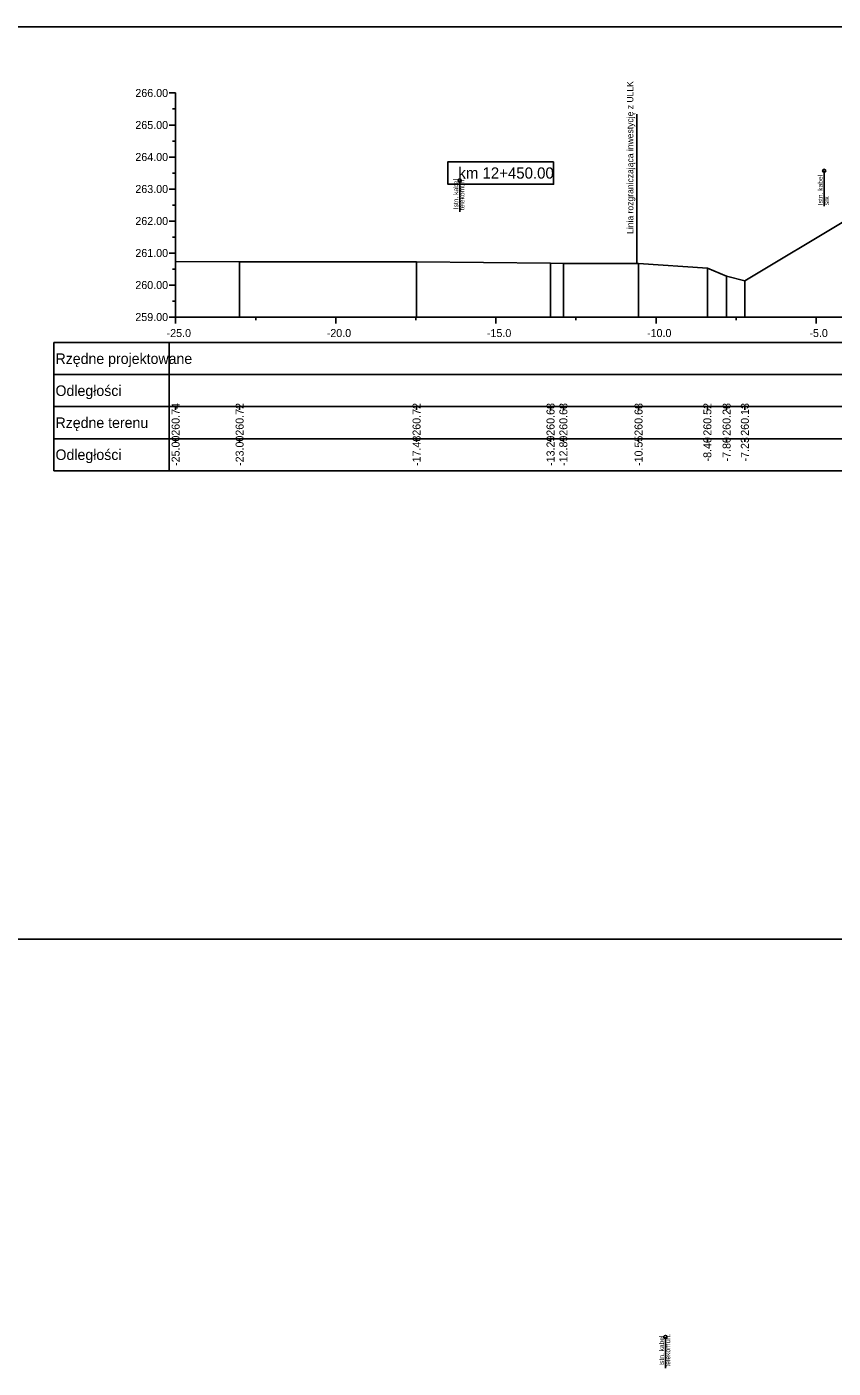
# Model space of a CAD drawing. Extents: x 6516023 to 6560129, y 5513077 to 5529206.
# Drawn here: x 6516864.76 to 6516889.94, y 5513349.38 to 5513391.29 of the extents above; entities that cross this region are included whole.
import ezdxf

# ---------------------------------------------------------------- set-up
doc = ezdxf.new("R2010")
doc.units = 0
for name, color, linetype in [('TOR_PRZEK_P-kable', 7, 'Continuous'), ('TOR_PRZEK_P-tabelka istniejace', 7, 'Continuous'), ('TOR_PRZEK_P-tabelka projektowane', 7, 'Continuous'), ('TOR_PRZEK_P-teren istniejacy', 7, 'Continuous'), ('TOR_PRZEK_P-uklad odniesienia', 7, 'Continuous'), ('TOR_PS_T-granica PKP-projektowana', 7, 'Continuous'), ('TOR_RAMKI-ramka+tabelka 1', 7, 'Continuous')]:
    doc.layers.add(name, color=color, linetype=linetype)

msp = doc.modelspace()

# ---------------------------------------------------------------- linework, layer by layer
at = {"layer": 'TOR_PRZEK_P-kable'}
for p, q in [((6516889.66, 5513386.791), (6516889.66, 5513385.682)), ((6516878.279, 5513386.488), (6516878.279, 5513385.514)), ((6516884.704, 5513350.355), (6516884.704, 5513349.382))]:
    msp.add_line(p, q, dxfattribs=at)
for centre in [(6516878.279, 5513386.488), (6516889.66, 5513386.791), (6516884.704, 5513350.355)]:
    msp.add_circle(centre, 0.05, dxfattribs=at)
at = {"layer": 'TOR_PRZEK_P-tabelka istniejace'}
for p, q in [((6516865.61, 5513379.422), (6516865.61, 5513377.422)), ((6516869.21, 5513379.422), (6516869.21, 5513377.422)), ((6516869.41, 5513379.322), (6516869.41, 5513379.422)), ((6516871.408, 5513379.322), (6516871.408, 5513379.422)), ((6516876.933, 5513379.322), (6516876.933, 5513379.422)), ((6516881.116, 5513379.322), (6516881.116, 5513379.422)), ((6516881.517, 5513379.322), (6516881.517, 5513379.422)), ((6516883.864, 5513379.322), (6516883.864, 5513379.422)), ((6516886.013, 5513379.322), (6516886.013, 5513379.422)), ((6516886.613, 5513379.322), (6516886.613, 5513379.422)), ((6516887.184, 5513379.322), (6516887.184, 5513379.422)), ((6516865.61, 5513378.422), (6516919.41, 5513378.422)), ((6516869.41, 5513378.322), (6516869.41, 5513378.422)), ((6516871.408, 5513378.322), (6516871.408, 5513378.422)), ((6516876.933, 5513378.322), (6516876.933, 5513378.422)), ((6516881.116, 5513378.322), (6516881.116, 5513378.422)), ((6516881.517, 5513378.322), (6516881.517, 5513378.422)), ((6516883.864, 5513378.322), (6516883.864, 5513378.422)), ((6516886.013, 5513378.322), (6516886.013, 5513378.422)), ((6516886.613, 5513378.322), (6516886.613, 5513378.422)), ((6516887.184, 5513378.322), (6516887.184, 5513378.422))]:
    msp.add_line(p, q, dxfattribs=at)
for points in [[(6516869.41, 5513383.96), (6516869.41, 5513382.422), (6516869.41, 5513382.292), (6516869.41, 5513382.222)], [(6516871.408, 5513383.943), (6516871.408, 5513382.422), (6516871.408, 5513382.292), (6516871.408, 5513382.222)], [(6516876.933, 5513383.943), (6516876.933, 5513382.422), (6516876.933, 5513382.292), (6516876.933, 5513382.222)], [(6516881.116, 5513383.902), (6516881.116, 5513382.422), (6516881.116, 5513382.292), (6516881.116, 5513382.222)], [(6516881.517, 5513383.898), (6516881.517, 5513382.422), (6516881.517, 5513382.292), (6516881.517, 5513382.222)], [(6516883.864, 5513383.898), (6516883.864, 5513382.422), (6516883.864, 5513382.292), (6516883.864, 5513382.222)], [(6516886.013, 5513383.744), (6516886.013, 5513382.422), (6516886.013, 5513382.292), (6516886.013, 5513382.222)], [(6516886.613, 5513383.499), (6516886.613, 5513382.422), (6516886.613, 5513382.292), (6516886.613, 5513382.222)], [(6516887.184, 5513383.35), (6516887.184, 5513382.422), (6516887.184, 5513382.292), (6516887.184, 5513382.222)]]:
    msp.add_lwpolyline(points, dxfattribs=at)
msp.add_lwpolyline([(6516865.61, 5513379.422), (6516865.61, 5513377.422), (6516919.41, 5513377.422), (6516919.41, 5513379.422)], close=True, dxfattribs=at)
at = {"layer": 'TOR_PRZEK_P-tabelka projektowane'}
for p, q in [((6516865.61, 5513381.422), (6516865.61, 5513379.422)), ((6516869.21, 5513381.422), (6516869.21, 5513379.422)), ((6516865.61, 5513380.422), (6516919.41, 5513380.422))]:
    msp.add_line(p, q, dxfattribs=at)
msp.add_lwpolyline([(6516865.61, 5513381.422), (6516865.61, 5513379.422), (6516919.41, 5513379.422), (6516919.41, 5513381.422)], close=True, dxfattribs=at)
at = {"layer": 'TOR_PRZEK_P-teren istniejacy'}
msp.add_lwpolyline([(6516869.41, 5513383.96), (6516871.408, 5513383.943), (6516876.933, 5513383.943), (6516881.116, 5513383.902), (6516881.517, 5513383.898), (6516883.864, 5513383.898), (6516886.013, 5513383.744), (6516886.613, 5513383.499), (6516887.184, 5513383.35), (6516890.381, 5513385.273)], dxfattribs=at)
at = {"layer": 'TOR_PRZEK_P-uklad odniesienia'}
for p, q in [((6516869.21, 5513389.222), (6516869.41, 5513389.222)), ((6516869.41, 5513389.222), (6516869.41, 5513382.222)), ((6516869.31, 5513388.722), (6516869.41, 5513388.722)), ((6516869.21, 5513388.222), (6516869.41, 5513388.222)), ((6516869.31, 5513387.722), (6516869.41, 5513387.722)), ((6516869.21, 5513387.222), (6516869.41, 5513387.222)), ((6516869.31, 5513386.722), (6516869.41, 5513386.722)), ((6516869.21, 5513386.222), (6516869.41, 5513386.222)), ((6516869.31, 5513385.722), (6516869.41, 5513385.722)), ((6516869.21, 5513385.222), (6516869.41, 5513385.222)), ((6516869.31, 5513384.722), (6516869.41, 5513384.722)), ((6516869.21, 5513384.222), (6516869.41, 5513384.222)), ((6516869.31, 5513383.722), (6516869.41, 5513383.722)), ((6516869.21, 5513383.222), (6516869.41, 5513383.222)), ((6516869.31, 5513382.722), (6516869.41, 5513382.722)), ((6516869.21, 5513382.222), (6516869.41, 5513382.222)), ((6516869.41, 5513382.222), (6516919.41, 5513382.222)), ((6516869.41, 5513382.022), (6516869.41, 5513382.222)), ((6516871.91, 5513382.122), (6516871.91, 5513382.222)), ((6516874.41, 5513382.022), (6516874.41, 5513382.222)), ((6516876.91, 5513382.122), (6516876.91, 5513382.222)), ((6516879.41, 5513382.022), (6516879.41, 5513382.222)), ((6516881.91, 5513382.122), (6516881.91, 5513382.222)), ((6516884.41, 5513382.022), (6516884.41, 5513382.222)), ((6516886.91, 5513382.122), (6516886.91, 5513382.222)), ((6516889.41, 5513382.022), (6516889.41, 5513382.222))]:
    msp.add_line(p, q, dxfattribs=at)
msp.add_lwpolyline([(6516881.21, 5513387.072), (6516877.91, 5513387.072), (6516877.91, 5513386.372), (6516881.21, 5513386.372)], close=True, dxfattribs=at)
at = {"layer": 'TOR_PS_T-granica PKP-projektowana'}
msp.add_line((6516883.814, 5513383.898), (6516883.814, 5513388.556), dxfattribs=at)
at = {"layer": 'TOR_RAMKI-ramka+tabelka 1'}
msp.add_lwpolyline([(6516805.96, 5513391.289), (6517053.46, 5513391.289), (6517053.46, 5513362.789), (6516805.96, 5513362.789)], close=True, dxfattribs=at)

# ---------------------------------------------------------------- texts
at = {"layer": 'TOR_PRZEK_P-kable'}
for s, height, p in [('telekomun.', 0.15, (6516878.428, 5513385.562)), ('Istn. kabel', 0.14999, (6516889.615, 5513385.718)), ('Istn. kabel', 0.14999, (6516878.234, 5513385.59)), ('srk', 0.15, (6516889.809, 5513385.718)), ('Istn. kabel', 0.14999, (6516884.659, 5513349.458)), ('telekomun.', 0.15, (6516884.854, 5513349.43))]:
    msp.add_text(s, height=height, rotation=90.0511, dxfattribs=at).set_placement(p)
at = {"layer": 'TOR_PRZEK_P-tabelka istniejace'}
for s, p in [('260.74', (6516869.535, 5513378.514)), ('260.72', (6516871.533, 5513378.515)), ('260.72', (6516877.058, 5513378.515)), ('260.68', (6516881.241, 5513378.513)), ('260.68', (6516881.642, 5513378.513)), ('260.68', (6516883.989, 5513378.513)), ('260.52', (6516886.138, 5513378.515)), ('260.28', (6516886.738, 5513378.513)), ('260.13', (6516887.309, 5513378.513)), ('-25.00', (6516869.535, 5513377.57)), ('-23.00', (6516871.533, 5513377.57)), ('-17.48', (6516877.058, 5513377.569)), ('-13.29', (6516881.241, 5513377.57)), ('-12.89', (6516881.642, 5513377.57)), ('-10.55', (6516883.989, 5513377.569)), ('-8.40', (6516886.138, 5513377.71)), ('-7.80', (6516886.738, 5513377.71)), ('-7.23', (6516887.309, 5513377.709))]:
    msp.add_text(s, height=0.25, rotation=90, dxfattribs=at).set_placement(p)
for s, p in [('Rzędne terenu', (6516865.66, 5513378.757)), ('Odległości', (6516865.66, 5513377.757))]:
    msp.add_text(s, height=0.33, dxfattribs=at).set_placement(p)
at = {"layer": 'TOR_PRZEK_P-tabelka projektowane'}
for s, p in [('Rzędne projektowane', (6516865.66, 5513380.757)), ('Odległości', (6516865.66, 5513379.757))]:
    msp.add_text(s, height=0.33, dxfattribs=at).set_placement(p)
at = {"layer": 'TOR_PRZEK_P-uklad odniesienia'}
for s, height, p in [('266.00', 0.25, (6516868.152, 5513389.097)), ('265.00', 0.25, (6516868.152, 5513388.097)), ('264.00', 0.25, (6516868.152, 5513387.097)), ('km 12+450.00', 0.35, (6516878.238, 5513386.547)), ('263.00', 0.25, (6516868.152, 5513386.097)), ('262.00', 0.25, (6516868.152, 5513385.097)), ('261.00', 0.25, (6516868.152, 5513384.097)), ('260.00', 0.25, (6516868.152, 5513383.097)), ('259.00', 0.25, (6516868.152, 5513382.097)), ('-', 0.0001, (6516869.41, 5513382.222)), ('-25.0', 0.25, (6516869.129, 5513381.597)), ('-20.0', 0.25, (6516874.129, 5513381.597)), ('-15.0', 0.25, (6516879.129, 5513381.597)), ('-10.0', 0.25, (6516884.129, 5513381.597)), ('-5.0', 0.25, (6516889.199, 5513381.597))]:
    msp.add_text(s, height=height, dxfattribs=at).set_placement(p)
at = {"layer": 'TOR_PS_T-granica PKP-projektowana'}
msp.add_text('Linia rozgraniczająca inwestycję z ULLK', height=0.2, rotation=90.0511, dxfattribs=at).set_placement((6516883.704, 5513384.82))

doc.saveas('drawing.dxf')
